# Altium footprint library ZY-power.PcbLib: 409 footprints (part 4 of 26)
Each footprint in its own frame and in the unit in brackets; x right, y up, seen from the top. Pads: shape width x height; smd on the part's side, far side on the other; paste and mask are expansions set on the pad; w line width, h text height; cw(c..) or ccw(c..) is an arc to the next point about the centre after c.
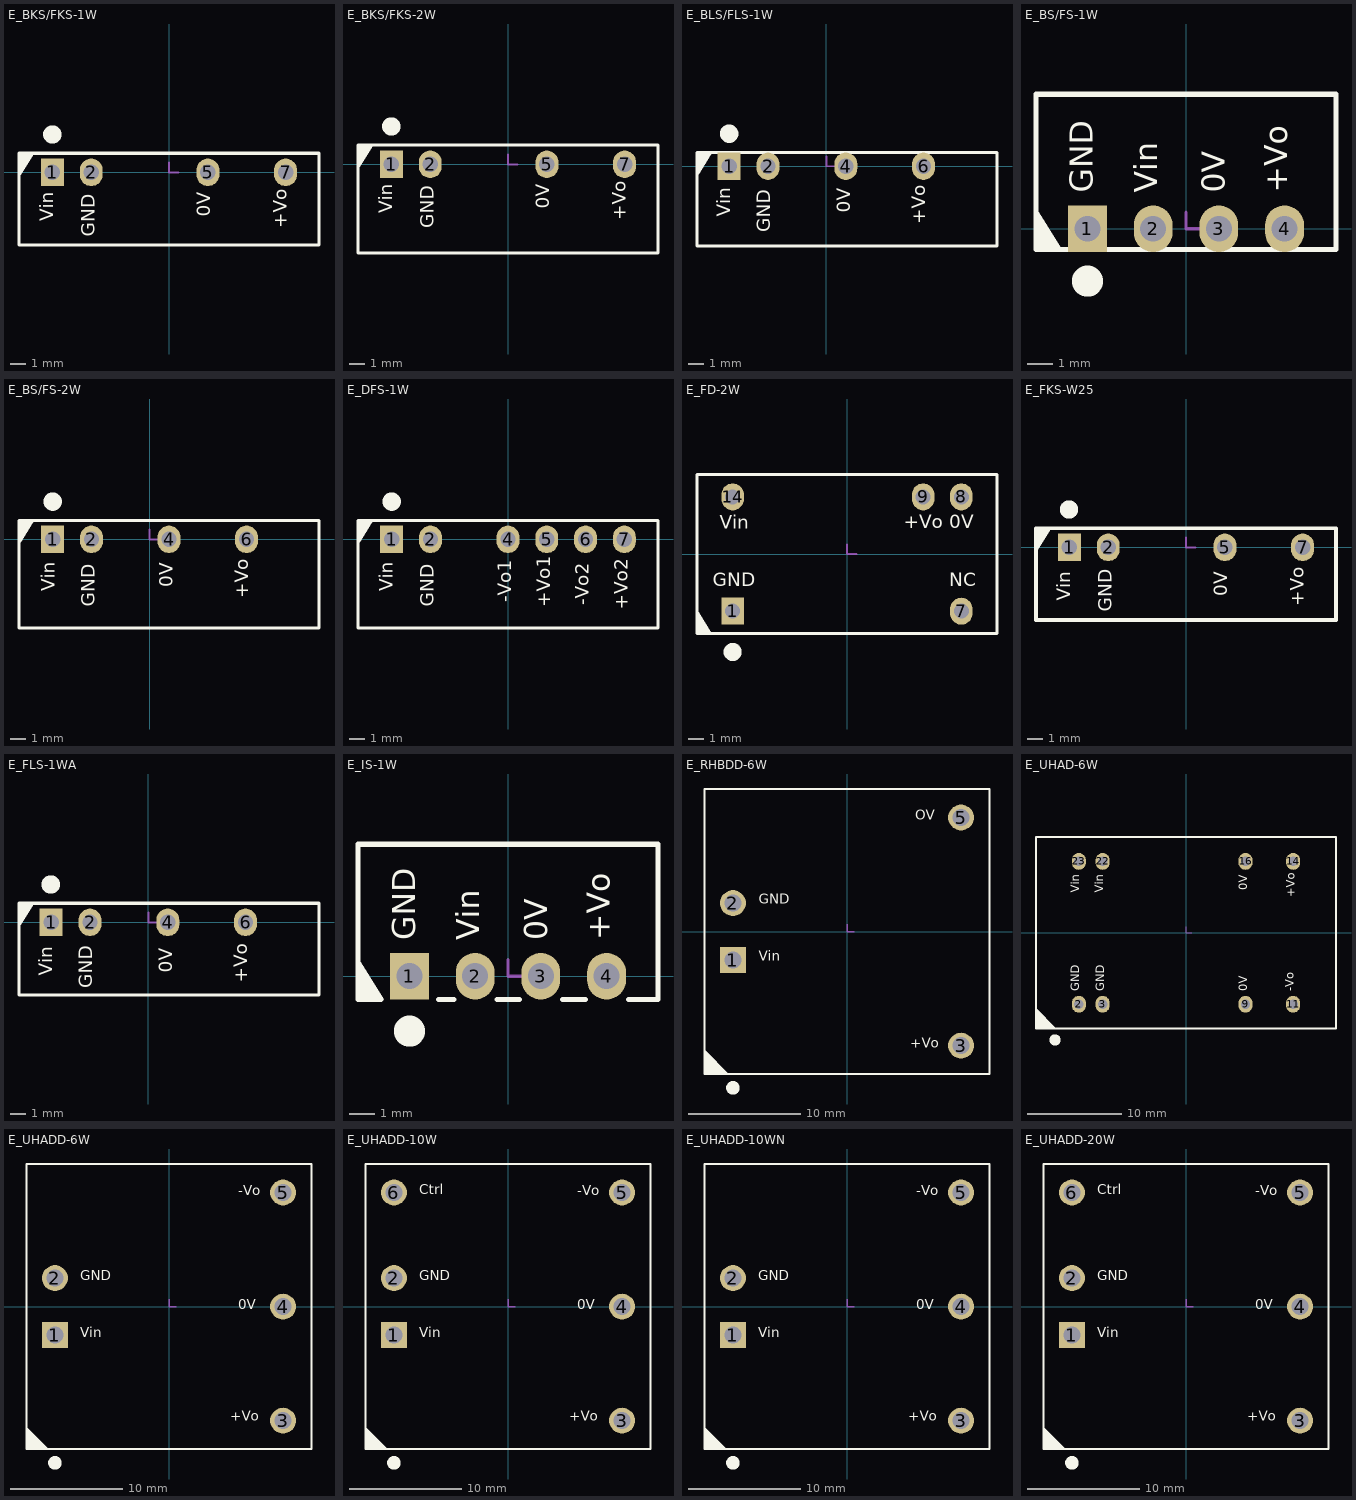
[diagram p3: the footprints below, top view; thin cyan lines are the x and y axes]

## E_BKS/FKS-1W [mm]
height 10
pads (4):
  rect 1.5x1.8 hole 1: 1(-7.62,0)
  oval 1.5x1.8 hole 1: 2(-5.08,0) 5(2.54,0) 7(7.62,0)
Top Overlay:
  circle w1: c-7.62,2.475 r0.1
  region: -9.8,-0.336 -9.8,1.25 -8.806,1.25
  lines w0.2: -9.8,-4.75 9.8,-4.75 9.8,1.25 -9.8,1.25 -9.8,-4.75
  text "Vin" at -7.275,-3.181 h1.52
  text "GND" at -4.572,-4.191 h1.52
  text "0V" at 3,-2.909 h1.52
  text "+Vo" at 8,-3.649 h1.52
Mechanical 15:
  lines w0.127: 0,0.635 0,0 0.635,0

## E_BKS/FKS-2W [mm]
height 10
pads (4):
  rect 1.5x1.8 hole 1: 1(-7.62,0)
  oval 1.5x1.8 hole 1: 2(-5.08,0) 5(2.54,0) 7(7.62,0)
Top Overlay:
  circle w1: c-7.62,2.475 r0.1
  region: -9.8,-0.336 -9.8,1.25 -8.806,1.25
  lines w0.2: -9.8,-5.8 -9.8,1.25 9.8,1.25 9.8,-5.8 -9.8,-5.8
  text "Vin" at -7.275,-3.181 h1.52
  text "GND" at -4.572,-4.191 h1.52
  text "0V" at 3,-2.909 h1.52
  text "+Vo" at 8,-3.649 h1.52
Mechanical 15:
  lines w0.127: 0,0.635 0,0 0.635,0

## E_BLS/FLS-1W [mm]
height 10
pads (4):
  rect 1.5x1.8 hole 1: 1(-6.35,0)
  oval 1.5x1.8 hole 1: 2(-3.81,0) 4(1.27,0) 6(6.35,0)
Top Overlay:
  circle w1: c-6.35,2.125 r0.1
  region: -8.45,-0.686 -8.45,0.9 -7.456,0.9
  lines w0.2: -8.45,-5.2 11.15,-5.2 11.15,0.9 -8.45,0.9 -8.45,-5.2
  text "Vin" at -5.969,-3.308 h1.52
  text "GND" at -3.378,-4.318 h1.52
  text "0V" at 1.854,-3.036 h1.52
  text "+Vo" at 6.756,-3.776 h1.52
Mechanical 15:
  lines w0.127: 0,0.635 0,0 0.635,0

## E_BS/FS-1W [mm]
height 10.1
pads (4):
  rect 1.5x1.8 hole 1: 1(-3.81,0)
  oval 1.5x1.8 hole 1: 2(-1.27,0) 3(1.27,0) 4(3.81,0)
Top Overlay:
  circle w1: c-3.81,-2.025 r0.1
  region: -5.8,0.786 -5.8,-0.8 -4.806,-0.8
  lines w0.2: 2.045,-0.8 4.636,-0.8 5.8,-0.8 ; 5.8,-0.8 -5.8,-0.8 -5.8,5.2 5.8,5.2 5.8,-0.8
  text "+Vo" at 4.204,1.396 h1.52
  text "0V" at 1.791,1.396 h1.52
  text "Vin" at -0.826,1.397 h1.52
  text "GND" at -3.315,1.396 h1.52
Mechanical 15:
  lines w0.127: 0,0.635 0,0 0.635,0

## E_BS/FS-2W [mm]
height 10.1
pads (4):
  rect 1.5x1.8 hole 1: 1(-6.35,0)
  oval 1.5x1.8 hole 1: 2(-3.81,0) 4(1.27,0) 6(6.35,0)
Top Overlay:
  circle w1: c-6.35,2.475 r0.1
  region: -8.555,-0.336 -8.555,1.25 -7.561,1.25
  lines w0.2: -8.555,-5.8 11.095,-5.8 11.095,1.25 -8.555,1.25 -8.555,-5.8
  text "Vin" at -5.93,-3.398 h1.52
  text "GND" at -3.302,-4.408 h1.52
  text "0V" at 1.795,-3.126 h1.52
  text "+Vo" at 6.745,-3.866 h1.52
Mechanical 15:
  lines w0.127: 0,0.635 0,0 0.635,0

## E_DFS-1W [mm]
height 10.1
pads (6):
  rect 1.5x1.8 hole 1: 1(-7.62,0)
  oval 1.5x1.8 hole 1: 2(-5.08,0) 4(0,0) 5(2.54,0) 6(5.08,0) 7(7.62,0)
Top Overlay:
  circle w1: c-7.62,2.475 r0.1
  region: -9.825,-0.336 -9.825,1.25 -8.831,1.25
  lines w0.2: -9.825,-5.8 -9.825,1.25 9.825,1.25 9.825,-5.8 -9.825,-5.8
  text "-Vo1" at 0.508,-4.128 h1.52
  text "Vin" at -7.239,-3.414 h1.52
  text "GND" at -4.572,-4.424 h1.52
  text "+Vo1" at 3.048,-4.44 h1.52
  text "-Vo2" at 5.588,-4.307 h1.52
  text "+Vo2" at 8.128,-4.619 h1.52

## E_FD-2W [mm]
height 8.1
pads (5):
  rect 1.5x1.8 hole 1 paste-0.787: 1(-7.62,-3.81)
  oval 1.5x1.8 hole 1 paste-0.787: 7(7.62,-3.81) 8(7.62,3.81) 9(5.08,3.81) 14(-7.62,3.81)
Top Overlay:
  circle w1: c-7.62,-6.525 r0.1
  region: -10,-3.714 -10,-5.3 -9.006,-5.3
  lines w0.2: -10,-5.3 10,-5.3 10,5.3 -10,5.3 -10,-5.3
  text "GND" at -8.941,-2.438 h1.52
  text "Vin" at -8.484,1.397 h1.52
  text "+Vo" at 3.785,1.422 h1.52
  text "0V" at 6.807,1.422 h1.52
  text "NC" at 6.807,-2.438 h1.52
Mechanical 15:
  lines w0.127: 0,0.635 0,0 0.635,0

## E_FKS-W25 [mm]
height 10.1
pads (4):
  rect 1.5x1.8 hole 1: 1(-7.62,0)
  oval 1.5x1.8 hole 1: 2(-5.08,0) 5(2.54,0) 7(7.62,0)
Top Overlay:
  circle w1: c-7.644,2.475 r0.1
  region: -9.8,-0.336 -9.8,1.25 -8.806,1.25
  lines w0.254: -9.8,-4.75 9.8,-4.75 9.8,1.25 -9.8,1.25 -9.8,-4.75
  text "Vin" at -7.275,-3.475 h1.52
  text "GND" at -4.572,-4.191 h1.52
  text "0V" at 3,-3.196 h1.52
  text "+Vo" at 8,-3.85 h1.52
Mechanical 15:
  lines w0.127: 0,0.635 0,0 0.635,0

## E_FLS-1WA [mm]
height 10.1
pads (4):
  rect 1.5x1.8 hole 1: 1(-6.35,0)
  oval 1.5x1.8 hole 1: 2(-3.81,0) 4(1.27,0) 6(6.35,0)
Top Overlay:
  circle w1: c-6.374,2.475 r0.1
  region: -8.45,-0.336 -8.45,1.25 -7.456,1.25
  lines w0.2: -8.45,-4.75 11.15,-4.75 11.15,1.25 -8.45,1.25 -8.45,-4.75
  text "+Vo" at 6.756,-3.937 h1.52
  text "0V" at 1.854,-3.302 h1.52
  text "GND" at -3.378,-4.318 h1.52
  text "Vin" at -5.969,-3.48 h1.52
Mechanical 15:
  lines w0.127: 0,0.635 0,0 0.635,0

## E_IS-1W [mm]
height 6
pads (4):
  rect 1.5x1.8 hole 1: 1(-3.81,0)
  oval 1.5x1.8 hole 1: 2(-1.27,0) 3(1.27,0) 4(3.81,0)
Top Overlay:
  circle w1: c-3.81,-2.125 r0.1
  region: -5.8,0.686 -5.8,-0.889 -4.813,-0.889
  lines w0.2: -4.91,-0.9 -5.8,-0.9 -5.8,5.1 5.8,5.1 5.8,-0.9 4.656,-0.9 ; -2.69,-0.9 -2.09,-0.9 ; -0.424,-0.9 0.45,-0.9 ; 2.116,-0.9 2.99,-0.9
  text "GND" at -3.302,1.396 h1.52
  text "Vin" at -0.813,1.397 h1.52
  text "0V" at 1.803,1.396 h1.52
  text "+Vo" at 4.216,1.396 h1.52
Mechanical 15:
  lines w0.127: 0,0.635 0,0 0.635,0
3D body "zhenjao01.stp": height 8.36, standoff -4.08, extent 3.11,-0.12 4.51,1.48
3D body "zhenjao01.stp": height 8.36, standoff -4.08, extent 0.57,-0.12 1.97,1.48
3D body "zhenjao01.stp": height 8.36, standoff -4.08, extent -1.97,-0.12 -0.57,1.48
3D body: height 10.1, standoff 0, extent -5.8,-0.9 5.8,5.1
3D body "zhenjao01.stp": height 8.36, standoff -4.08, extent -4.51,-0.12 -3.11,1.48

## E_RHBDD-6W [mm]
height 11.7
pads (4):
  rect 2.3x2.3 hole 1.5: 1(-10.16,-2.54)
  round 2.3 hole 1.5: 2(-10.16,2.54) 3(10.16,-10.16) 5(10.16,10.16)
Top Overlay:
  circle w1: c-10.16,-13.925 r0.1
  region: -12.598,-12.603 -10.623,-12.603 -12.598,-10.628
  lines w0.2: -12.7,-12.7 12.7,-12.7 12.7,12.7 -12.7,12.7 -12.7,-12.7
  text "+Vo" at 5.649,-10.668 h1.52
  text "OV" at 6.096,9.652 h1.52
  text "GND" at -7.874,2.159 h1.52
  text "Vin" at -7.873,-2.921 h1.52
Mechanical 15:
  lines w0.127: 0,0.635 0,0 0.635,0

## E_UHAD-6W [mm]
height 11
pads (8):
  oval 1.5x1.8 hole 1: 2(-11.43,-7.62) 3(-8.89,-7.62) 9(6.35,-7.62) 11(11.43,-7.62) 14(11.43,7.62) 16(6.35,7.62) 22(-8.89,7.62) 23(-11.43,7.62)
Top Overlay:
  circle w1: c-13.97,-11.425 r0.1
  region: -15.898,-10.103 -13.923,-10.103 -15.898,-8.128
  lines w0.2: -16,-10.2 16,-10.2 16,10.2 -16,10.2 -16,-10.2
  text "0V" at 6.833,-6.223 h1.52
  text "0V" at 6.858,4.55 h1.52
  text "+Vo" at 11.938,3.81 h1.52
  text "-Vo" at 11.811,-6.223 h1.52
  text "Vin" at -8.509,4.278 h1.52
  text "Vin" at -11.049,4.278 h1.52
  text "GND" at -8.382,-6.223 h1.52
  text "GND" at -11.049,-6.223 h1.52
Mechanical 15:
  lines w0.127: 0,0.635 0,0 0.635,0

## E_UHADD-6W [mm]
height 11.8
pads (5):
  rect 2.3x2.3 hole 1.5: 1(-10.16,-2.54)
  round 2.3 hole 1.5: 2(-10.16,2.54) 3(10.16,-10.16) 4(10.16,0) 5(10.16,10.16)
Top Overlay:
  circle w1: c-10.16,-13.925 r0.1
  region: -12.7,-12.7 -10.725,-12.7 -12.7,-10.725
  lines w0.2: -12.7,-12.7 -12.7,12.7 12.7,12.7 12.7,-12.7 -12.7,-12.7
  text "-Vo" at 6.175,9.625 h1.52
  text "+Vo" at 5.435,-10.5 h1.52
  text "0V" at 6.175,-0.535 h1.52
  text "GND" at -7.901,2.05 h1.52
  text "Vin" at -7.9,-3.025 h1.52
Mechanical 15:
  lines w0.127: 0,0.635 0,0 0.635,0
3D body: height -1.1, standoff -6.01, extent 9.664,-0.499 10.66,0.499
3D body: height 11.8, standoff 0, extent -12.7,-12.7 12.7,12.7
3D body: height -1.1, standoff -6.01, extent -10.656,2.041 -9.66,3.039
3D body: height -1.1, standoff -6.01, extent -10.656,-3.039 -9.66,-2.041
3D body: height -1.1, standoff -6.01, extent 9.664,-10.659 10.66,-9.661
3D body: height -1.1, standoff -6.01, extent 9.664,9.661 10.66,10.659

## E_UHADD-10W [mm]
height 11.7
pads (6):
  rect 2.3x2.3 hole 1.5: 1(-10.16,-2.54)
  round 2.3 hole 1.5: 2(-10.16,2.54) 3(10.16,-10.16) 4(10.16,0) 5(10.16,10.16) 6(-10.16,10.16)
Top Overlay:
  circle w1: c-10.16,-13.925 r0.1
  region: -12.7,-12.7 -10.725,-12.7 -12.7,-10.725
  lines w0.2: -12.7,-12.7 12.7,-12.7 12.7,12.7 -12.7,12.7 -12.7,-12.7
  text "-Vo" at 6.175,9.625 h1.52
  text "+Vo" at 5.435,-10.5 h1.52
  text "Ctrl" at -7.901,9.7 h1.52
  text "Vin" at -7.9,-3.025 h1.52
  text "GND" at -7.901,2.05 h1.52
  text "0V" at 6.175,-0.535 h1.52
Mechanical 15:
  lines w0.127: 0,0.635 0,0 0.635,0
3D body: height -1.1, standoff -6.01, extent 9.664,-0.499 10.66,0.499
3D body: height -1.1, standoff -6.01, extent -10.656,9.661 -9.66,10.659
3D body: height -1.1, standoff -6.01, extent 9.664,9.661 10.66,10.659
3D body: height -1.1, standoff -6.01, extent 9.664,-10.659 10.66,-9.661
3D body: height -1.1, standoff -6.01, extent -10.656,-3.039 -9.66,-2.041
3D body: height -1.1, standoff -6.01, extent -10.656,2.041 -9.66,3.039
3D body: height 11.8, standoff 0, extent -12.7,-12.7 12.7,12.7

## E_UHADD-10WN [mm]
height 11.7
pads (5):
  rect 2.3x2.3 hole 1.5: 1(-10.16,-2.54)
  round 2.3 hole 1.5: 2(-10.16,2.54) 3(10.16,-10.16) 4(10.16,0) 5(10.16,10.16)
Top Overlay:
  circle w1: c-10.16,-13.925 r0.1
  region: -12.7,-12.7 -10.725,-12.7 -12.7,-10.725
  lines w0.2: -12.7,-12.7 -12.7,12.7 12.7,12.7 12.7,-12.7 -12.7,-12.7
  text "0V" at 6.175,-0.535 h1.52
  text "GND" at -7.901,2.05 h1.52
  text "Vin" at -7.9,-3.025 h1.52
  text "+Vo" at 5.435,-10.5 h1.52
  text "-Vo" at 6.175,9.625 h1.52
Mechanical 15:
  lines w0.127: 0,0.635 0,0 0.635,0
3D body: height -1.1, standoff -6.01, extent 9.664,9.661 10.66,10.659
3D body: height -1.1, standoff -6.01, extent 9.664,-10.659 10.66,-9.661
3D body: height -1.1, standoff -6.01, extent -10.656,-3.039 -9.66,-2.041
3D body: height -1.1, standoff -6.01, extent -10.656,2.041 -9.66,3.039
3D body: height 11.8, standoff 0, extent -12.7,-12.7 12.7,12.7
3D body: height -1.1, standoff -6.01, extent 9.664,-0.499 10.66,0.499

## E_UHADD-20W [mm]
height 11.7
pads (6):
  rect 2.3x2.3 hole 1.5: 1(-10.16,-2.54)
  round 2.3 hole 1.5: 2(-10.16,2.54) 3(10.16,-10.16) 4(10.16,0) 5(10.16,10.16) 6(-10.16,10.16)
Top Overlay:
  circle w1: c-10.16,-13.925 r0.1
  region: -12.7,-12.7 -10.725,-12.7 -12.7,-10.725
  lines w0.2: -12.7,-12.7 -12.7,12.7 12.7,12.7 12.7,-12.7 -12.7,-12.7
  text "0V" at 6.175,-0.535 h1.52
  text "GND" at -7.901,2.05 h1.52
  text "Vin" at -7.9,-3.025 h1.52
  text "Ctrl" at -7.901,9.7 h1.52
  text "+Vo" at 5.435,-10.5 h1.52
  text "-Vo" at 6.175,9.625 h1.52
Mechanical 15:
  lines w0.127: 0,0.635 0,0 0.635,0
3D body: height 11.8, standoff 0, extent -12.7,-12.7 12.7,12.7
3D body: height -1.1, standoff -6.01, extent -10.656,2.041 -9.66,3.039
3D body: height -1.1, standoff -6.01, extent -10.656,-3.039 -9.66,-2.041
3D body: height -1.1, standoff -6.01, extent 9.664,-10.659 10.66,-9.661
3D body: height -1.1, standoff -6.01, extent 9.664,9.661 10.66,10.659
3D body: height -1.1, standoff -6.01, extent -10.656,9.661 -9.66,10.659
3D body: height -1.1, standoff -6.01, extent 9.664,-0.499 10.66,0.499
